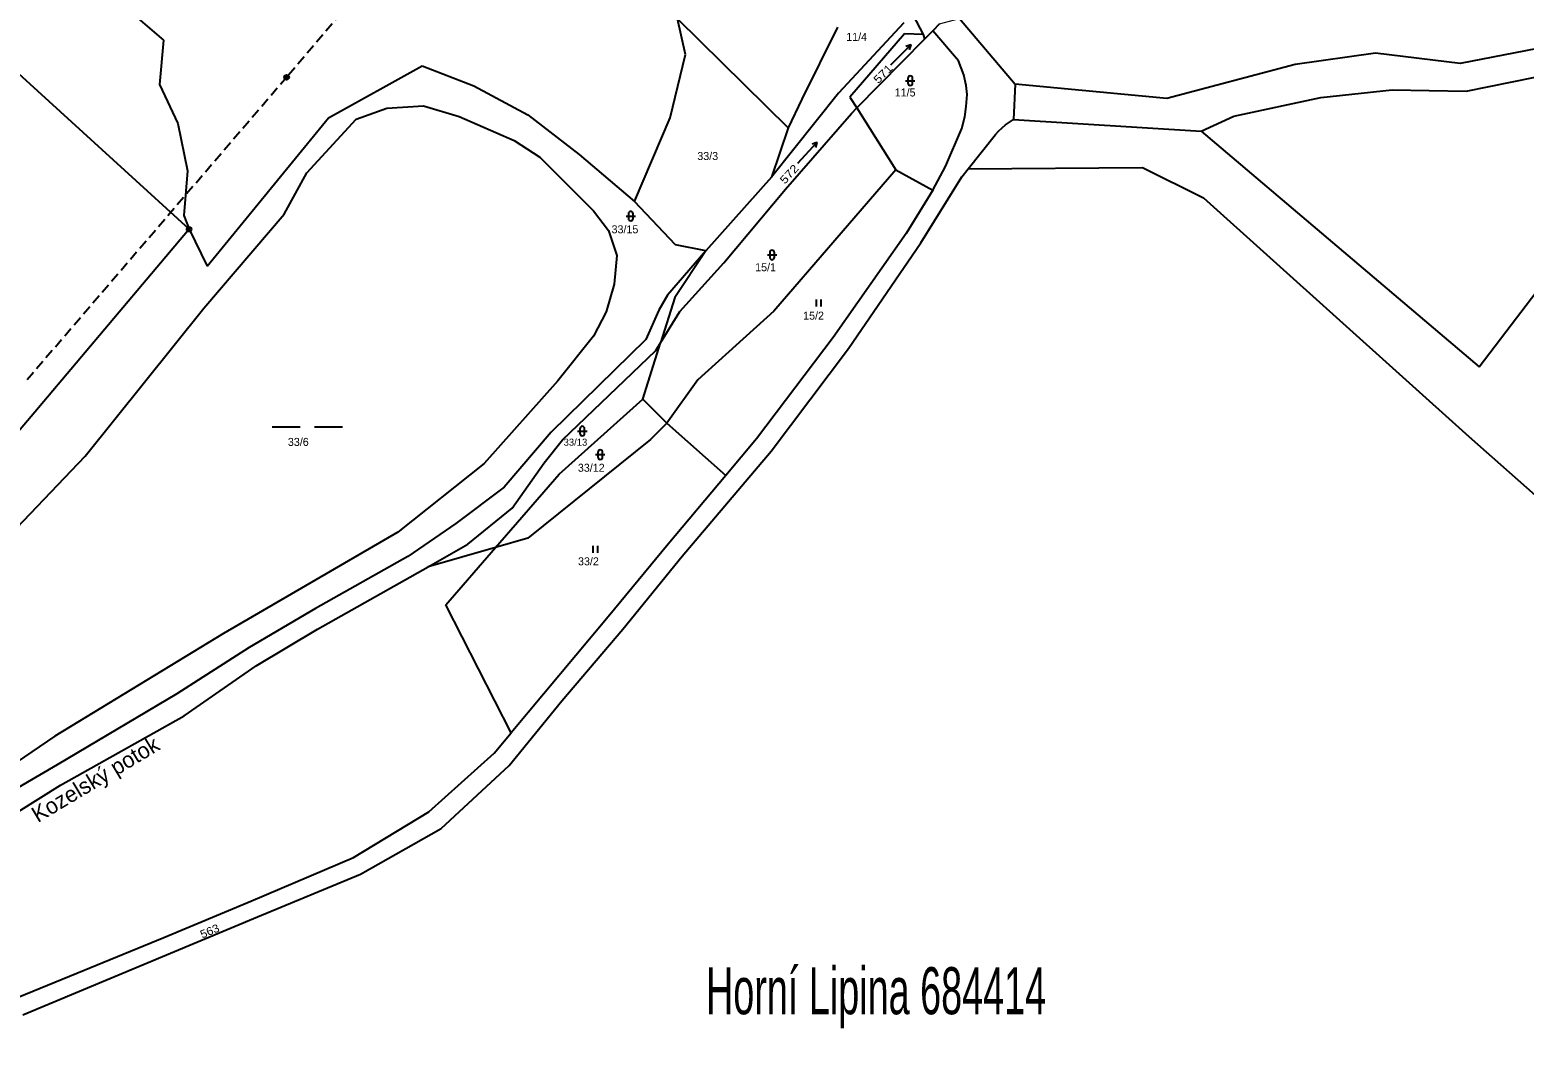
# Model space of a CAD drawing. Extents: x -885985 to -883535, y -1030025 to -1027941.
# Drawn here: x -884740.1 to -884422.7, y -1028775.1 to -1028559.6 of the extents above; entities that cross this region are included whole.
import ezdxf
from ezdxf.enums import TextEntityAlignment as Align

# ---------------------------------------------------------------- set-up
doc = ezdxf.new("R2010")
doc.units = 0
doc.header["$LTSCALE"] = 0.68
doc.linetypes.add('MEDIUM_DASHED', pattern=[4.5, 3, -1.5])
for name, color, linetype, lineweight in [('1', 7, 'Continuous', 25), ('13', 7, 'Continuous', 13), ('3', 7, 'Continuous', 25), ('6', 7, 'Continuous', 25), ('7', 7, 'Continuous', 13), ('8', 7, 'Continuous', 25)]:
    doc.layers.add(name, color=color, linetype=linetype, lineweight=lineweight)
doc.layers.add('2', color=7, linetype='Continuous')

msp = doc.modelspace()

# ---------------------------------------------------------------- linework, layer by layer
at = {"layer": '1'}
for p, q in [((-884706.28, -1028601.97), (-884797.58, -1028518.66)), ((-884434.95, -1028572.64), (-884308.01, -1028546.89)), ((-884725.57, -1028549.84), (-884711.72, -1028561.82)), ((-884602.56, -1028557.23), (-884579.05, -1028580.4)), ((-884600.83, -1028564.87), (-884602.56, -1028557.23)), ((-884550.25, -1028560.62), (-884552.45, -1028556.38)), ((-884542.63, -1028557.19), (-884530.79, -1028571.17)), ((-884384.12, -1028556.66), (-884436.23, -1028566.74)), ((-884568.51, -1028559.01), (-884576.14, -1028574.34)), ((-884554.43, -1028558.08), (-884568.33, -1028573.09)), ((-884554.3, -1028560.45), (-884565.89, -1028573.91)), ((-884550.25, -1028560.62), (-884554.3, -1028560.45)), ((-884549.96, -1028561.5), (-884550.25, -1028560.62)), ((-884548.28, -1028559.79), (-884549.96, -1028561.5)), ((-884546.85, -1028558.35), (-884548.28, -1028559.79)), ((-884542.86, -1028566.19), (-884548.28, -1028559.79)), ((-884711.72, -1028561.82), (-884712.6, -1028571.18)), ((-884564.46, -1028576.19), (-884549.96, -1028561.5)), ((-884676.69, -1028578.3), (-884656.74, -1028567.24)), ((-884656.74, -1028567.24), (-884645.82, -1028571.5)), ((-884604.11, -1028578.28), (-884600.83, -1028564.87)), ((-884541.73, -1028569.16), (-884542.86, -1028566.19)), ((-884471.28, -1028566.98), (-884498.57, -1028574.16)), ((-884454.23, -1028564.53), (-884471.28, -1028566.98)), ((-884436.23, -1028566.74), (-884454.23, -1028564.53)), ((-884541.21, -1028571.4), (-884541.73, -1028569.16)), ((-884712.6, -1028571.18), (-884708.69, -1028579.49)), ((-884645.82, -1028571.5), (-884634.31, -1028577.66)), ((-884568.33, -1028573.09), (-884582.54, -1028590.87)), ((-884540.98, -1028573.36), (-884541.21, -1028571.4)), ((-884541.21, -1028575.92), (-884540.98, -1028573.36)), ((-884530.79, -1028571.17), (-884531.16, -1028578.68)), ((-884498.57, -1028574.16), (-884530.79, -1028571.17)), ((-884465.84, -1028573.97), (-884450.73, -1028572.34)), ((-884450.73, -1028572.34), (-884434.95, -1028572.64)), ((-884670.77, -1028578.55), (-884664.29, -1028576.23)), ((-884664.29, -1028576.23), (-884656.5, -1028575.76)), ((-884656.5, -1028575.76), (-884648.88, -1028577.99)), ((-884576.14, -1028574.34), (-884579.05, -1028580.4)), ((-884565.89, -1028573.91), (-884564.46, -1028576.19)), ((-884565.59, -1028577.34), (-884564.46, -1028576.19)), ((-884564.46, -1028576.19), (-884556.15, -1028589.35)), ((-884541.52, -1028578.08), (-884541.21, -1028575.92)), ((-884484.34, -1028577.94), (-884465.84, -1028573.97)), ((-884708.69, -1028579.49), (-884706.62, -1028589.52)), ((-884702.45, -1028609.83), (-884676.69, -1028578.3)), ((-884681.27, -1028589.98), (-884670.77, -1028578.55)), ((-884648.88, -1028577.99), (-884637.19, -1028583.09)), ((-884634.31, -1028577.66), (-884623.44, -1028586.06)), ((-884611.69, -1028596.09), (-884604.11, -1028578.28)), ((-884579.61, -1028593.44), (-884565.59, -1028577.34)), ((-884542.09, -1028580.58), (-884541.52, -1028578.08)), ((-884533.59, -1028580.42), (-884532.82, -1028579.78)), ((-884532.82, -1028579.78), (-884532.01, -1028579.2)), ((-884532.01, -1028579.2), (-884531.16, -1028578.68)), ((-884531.16, -1028578.68), (-884491.25, -1028581.16)), ((-884491.25, -1028581.16), (-884484.34, -1028577.94)), ((-884432.19, -1028631.2), (-884391.65, -1028577.75)), ((-884637.19, -1028583.09), (-884631.8, -1028586.62)), ((-884579.05, -1028580.4), (-884582.54, -1028590.87)), ((-884545.57, -1028588.64), (-884542.09, -1028580.58)), ((-884540.77, -1028589.15), (-884534.98, -1028581.86)), ((-884534.98, -1028581.86), (-884534.31, -1028581.12)), ((-884534.31, -1028581.12), (-884533.59, -1028580.42)), ((-884491.25, -1028581.16), (-884432.19, -1028631.2)), ((-884623.44, -1028586.06), (-884611.69, -1028596.09)), ((-884631.8, -1028586.62), (-884620.35, -1028598.06)), ((-884556.15, -1028589.35), (-884582.05, -1028619.38)), ((-884556.15, -1028589.35), (-884548.27, -1028593.69)), ((-884548.27, -1028593.69), (-884545.57, -1028588.64)), ((-884542.1, -1028590.83), (-884540.77, -1028589.15)), ((-884540.77, -1028589.15), (-884503.73, -1028588.85)), ((-884503.73, -1028588.85), (-884490.78, -1028595.26)), ((-884706.62, -1028589.52), (-884707.39, -1028599.05)), ((-884686.05, -1028598.76), (-884681.27, -1028589.98)), ((-884582.54, -1028590.87), (-884596.48, -1028606.55)), ((-884550.8, -1028604.83), (-884542.1, -1028590.83)), ((-884592.7, -1028609.09), (-884579.61, -1028593.44)), ((-884548.27, -1028593.69), (-884553.98, -1028602.85)), ((-884490.78, -1028595.26), (-884434.45, -1028645.99)), ((-884703.13, -1028618.74), (-884686.05, -1028598.76)), ((-884620.35, -1028598.06), (-884617.18, -1028602.23)), ((-884602.98, -1028605.3), (-884611.69, -1028596.09)), ((-884706.28, -1028601.97), (-884738.26, -1028639.89)), ((-884707.39, -1028599.05), (-884706.28, -1028601.97)), ((-884706.28, -1028601.97), (-884702.45, -1028609.83)), ((-884617.18, -1028602.23), (-884615.39, -1028607.56)), ((-884596.48, -1028606.55), (-884602.98, -1028605.3)), ((-884553.98, -1028602.85), (-884569.47, -1028624.95)), ((-884566.18, -1028627.33), (-884550.8, -1028604.83)), ((-884615.39, -1028607.56), (-884615.97, -1028613.66)), ((-884596.48, -1028606.55), (-884604.65, -1028615.96)), ((-884596.48, -1028606.55), (-884603.11, -1028616.45)), ((-884602, -1028619.43), (-884592.7, -1028609.09)), ((-884615.97, -1028613.66), (-884617.68, -1028619.5)), ((-884604.65, -1028615.96), (-884606.5, -1028619.15)), ((-884603.11, -1028616.45), (-884606.12, -1028626.08)), ((-884728.36, -1028650.17), (-884703.13, -1028618.74)), ((-884617.68, -1028619.5), (-884620.38, -1028624.67)), ((-884606.5, -1028619.15), (-884609.23, -1028625.37)), ((-884606.12, -1028626.08), (-884602, -1028619.43)), ((-884582.05, -1028619.38), (-884598.2, -1028633.99)), ((-884609.23, -1028625.37), (-884629.37, -1028645.07)), ((-884620.38, -1028624.67), (-884627.94, -1028634.19)), ((-884609.87, -1028638.09), (-884606.12, -1028626.08)), ((-884607.11, -1028627.69), (-884606.12, -1028626.08)), ((-884569.47, -1028624.95), (-884585.76, -1028646.46)), ((-884582.6, -1028649.08), (-884566.18, -1028627.33)), ((-884626.94, -1028646.68), (-884607.11, -1028627.69)), ((-884627.94, -1028634.19), (-884643.61, -1028651.75)), ((-884598.2, -1028633.99), (-884604.78, -1028643.13)), ((-884738.26, -1028639.89), (-884768.69, -1028675.6)), ((-884627.65, -1028653.97), (-884609.87, -1028638.09)), ((-884604.78, -1028643.13), (-884609.87, -1028638.09)), ((-884604.78, -1028643.13), (-884608.28, -1028646.6)), ((-884604.78, -1028643.13), (-884592.28, -1028654.25)), ((-884629.37, -1028645.07), (-884639.34, -1028656.79)), ((-884608.28, -1028646.6), (-884634.35, -1028667.62)), ((-884585.76, -1028646.46), (-884592.28, -1028654.25)), ((-884434.45, -1028645.99), (-884409.59, -1028668.03)), ((-884630.82, -1028651.6), (-884626.94, -1028646.68)), ((-884601.5, -1028671.42), (-884582.6, -1028649.08)), ((-884757.19, -1028680.37), (-884728.36, -1028650.17)), ((-884643.61, -1028651.75), (-884661.93, -1028666.35)), ((-884637.64, -1028661.23), (-884630.82, -1028651.6)), ((-884641.2, -1028669.6), (-884627.65, -1028653.97)), ((-884592.28, -1028654.25), (-884604.54, -1028668.89)), ((-884639.34, -1028656.79), (-884649.65, -1028664.48)), ((-884647.09, -1028668.84), (-884637.64, -1028661.23)), ((-884649.65, -1028664.48), (-884659.83, -1028671.52)), ((-884661.93, -1028666.35), (-884698.99, -1028687.87)), ((-884634.35, -1028667.62), (-884641.2, -1028669.6)), ((-884659.83, -1028671.52), (-884679.43, -1028682.56)), ((-884655.47, -1028673.71), (-884647.09, -1028668.84)), ((-884641.2, -1028669.6), (-884655.47, -1028673.71)), ((-884651.76, -1028681.78), (-884641.2, -1028669.6)), ((-884604.54, -1028668.89), (-884617.25, -1028684.33)), ((-884614.13, -1028686.93), (-884601.5, -1028671.42)), ((-884679.02, -1028686.95), (-884655.47, -1028673.71)), ((-884679.43, -1028682.56), (-884693.5, -1028690.83)), ((-884637.85, -1028708.94), (-884651.76, -1028681.78)), ((-884617.25, -1028684.33), (-884637.85, -1028708.94)), ((-884698.99, -1028687.87), (-884734.79, -1028709.66)), ((-884692, -1028694.7), (-884679.02, -1028686.95)), ((-884627.07, -1028702.18), (-884614.13, -1028686.93)), ((-884693.5, -1028690.83), (-884708.9, -1028700.65)), ((-884707.33, -1028705.31), (-884692, -1028694.7)), ((-884708.9, -1028700.65), (-884734.34, -1028715.78)), ((-884638.29, -1028715.89), (-884627.07, -1028702.18)), ((-884733.63, -1028720.09), (-884707.33, -1028705.31)), ((-884734.79, -1028709.66), (-884746.13, -1028717.41)), ((-884641.46, -1028713.25), (-884637.85, -1028708.94)), ((-884655.37, -1028725.7), (-884641.46, -1028713.25)), ((-884734.34, -1028715.78), (-884764.82, -1028733.47)), ((-884652.72, -1028729.29), (-884638.29, -1028715.89)), ((-884763.06, -1028738.5), (-884733.63, -1028720.09)), ((-884671.33, -1028735.46), (-884655.37, -1028725.7)), ((-884669.87, -1028738.95), (-884652.72, -1028729.29)), ((-884693.16, -1028744.72), (-884671.33, -1028735.46)), ((-884691.78, -1028748.04), (-884669.87, -1028738.95)), ((-884711.63, -1028752.4), (-884693.16, -1028744.72)), ((-884710.22, -1028755.77), (-884691.78, -1028748.04)), ((-884730.12, -1028760.01), (-884711.63, -1028752.4)), ((-884741.61, -1028768.83), (-884710.22, -1028755.77)), ((-884767.18, -1028775.08), (-884730.12, -1028760.01))]:
    msp.add_line(p, q, dxfattribs=at)
at = {"layer": '13'}
msp.add_lwpolyline([(-884546.85, -1028558.35), (-884542.63, -1028557.19), (-884541.49, -1028556.22), (-884545.32, -1028551.02), (-884545.96, -1028551.56), (-884552.45, -1028556.38), (-884550.25, -1028560.62), (-884549.96, -1028561.5), (-884548.28, -1028559.79)], close=True, dxfattribs=at)
at = {"layer": '3'}
for p, q in [((-884552.981, -1028562.783), (-884553.317, -1028563.828)), ((-884554.091, -1028570.401), (-884552.089, -1028570.401)), ((-884553.591, -1028569.901), (-884553.591, -1028570.902)), ((-884552.589, -1028570.902), (-884552.589, -1028569.901)), ((-884572.896, -1028583.529), (-884573.196, -1028584.586)), ((-884612.961, -1028598.681), (-884612.961, -1028599.682)), ((-884611.959, -1028599.682), (-884611.959, -1028598.681)), ((-884613.461, -1028599.181), (-884611.459, -1028599.181)), ((-884583.441, -1028607.431), (-884581.439, -1028607.431)), ((-884582.941, -1028606.931), (-884582.941, -1028607.932)), ((-884581.939, -1028607.932), (-884581.939, -1028606.931)), ((-884572.991, -1028618.41), (-884572.991, -1028616.91)), ((-884571.99, -1028618.41), (-884571.99, -1028616.91)), ((-884688.659, -1028643.96), (-884682.659, -1028643.96)), ((-884679.659, -1028643.96), (-884673.659, -1028643.96)), ((-884623.751, -1028644.831), (-884621.749, -1028644.831)), ((-884623.251, -1028644.331), (-884623.251, -1028645.332)), ((-884622.249, -1028645.332), (-884622.249, -1028644.331)), ((-884619.441, -1028649.351), (-884619.441, -1028650.352)), ((-884618.439, -1028650.352), (-884618.439, -1028649.351)), ((-884619.941, -1028649.851), (-884617.939, -1028649.851)), ((-884620.461, -1028670.74), (-884620.461, -1028669.24)), ((-884619.46, -1028670.74), (-884619.46, -1028669.24))]:
    msp.add_line(p, q, dxfattribs=at)
for points in [[(-884557.223, -1028567.025), (-884552.981, -1028562.783), (-884554.026, -1028563.119)], [(-884576.988, -1028587.917), (-884572.896, -1028583.529), (-884573.929, -1028583.902)]]:
    msp.add_lwpolyline(points, dxfattribs=at)
for centre, start, end in [((-884553.09, -1028569.9009), 0, 180), ((-884553.09, -1028570.9009), 180, 359.98789), ((-884612.46, -1028598.6809), 0, 180), ((-884612.46, -1028599.6809), 180, 359.98789), ((-884582.44, -1028606.9309), 0, 180), ((-884582.44, -1028607.9309), 180, 359.98789), ((-884622.75, -1028644.3309), 0, 180), ((-884622.75, -1028645.3309), 180, 359.98789), ((-884618.94, -1028649.3509), 0, 180), ((-884618.94, -1028650.3509), 180, 359.98789)]:
    msp.add_arc(centre, 0.5, start, end, dxfattribs=at)
at = {"layer": '6', "linetype": 'MEDIUM_DASHED'}
for p, q in [((-884632.35, -1028506.99), (-884685.55, -1028569.69)), ((-884685.55, -1028569.69), (-884740.74, -1028634.04))]:
    msp.add_line(p, q, dxfattribs=at)
at = {"layer": '6'}
for radius in [0.5, 0.4, 0.3, 0.2, 0.1]:
    msp.add_circle((-884685.5534, -1028569.6899), radius, dxfattribs=at)
at = {"layer": '8'}
for radius in [0.5, 0.0303]:
    msp.add_circle((-884706.28, -1028601.9699), radius, dxfattribs=at)

# ---------------------------------------------------------------- texts
at = {"layer": '2'}
for s, height, p in [('11/4', 1.7, (-884566.68, -1028561.945)), ('11/5', 1.7, (-884556.38, -1028573.755)), ('33/3', 1.7, (-884598.32, -1028587.255)), ('33/15', 1.7, (-884616.53, -1028602.825)), ('15/1', 1.7, (-884586.03, -1028610.885)), ('15/2', 1.7, (-884575.84, -1028621.175)), ('33/6', 1.7, (-884685.29, -1028647.995)), ('33/13', 1.5, (-884626.72, -1028647.955)), ('33/12', 1.7, (-884623.69, -1028653.485)), ('33/2', 1.7, (-884623.66, -1028673.365))]:
    msp.add_text(s, height=height, dxfattribs=at).set_placement(p)
for s, rotation, width, p in [('571', 45, 1.2, (-884559.889, -1028571.16)), ('572', 47, 1.2, (-884579.729, -1028592.499)), ('563', 23, 1.1, (-884703.483, -1028752.671))]:
    msp.add_text(s, height=1.7, rotation=rotation, dxfattribs=dict(at, width=width)).set_placement(p)
at = {"layer": '7'}
msp.add_text('Kozelský potok', height=3.4, rotation=31, dxfattribs=at).set_placement((-884738.412, -1028728.138))
at = {"layer": '7', "width": 0.6}
msp.add_text('Horní Lipina 684414', height=10, dxfattribs=at).set_placement((-884560.339, -1028768.733), align=Align.CENTER)

doc.saveas('drawing.dxf')
